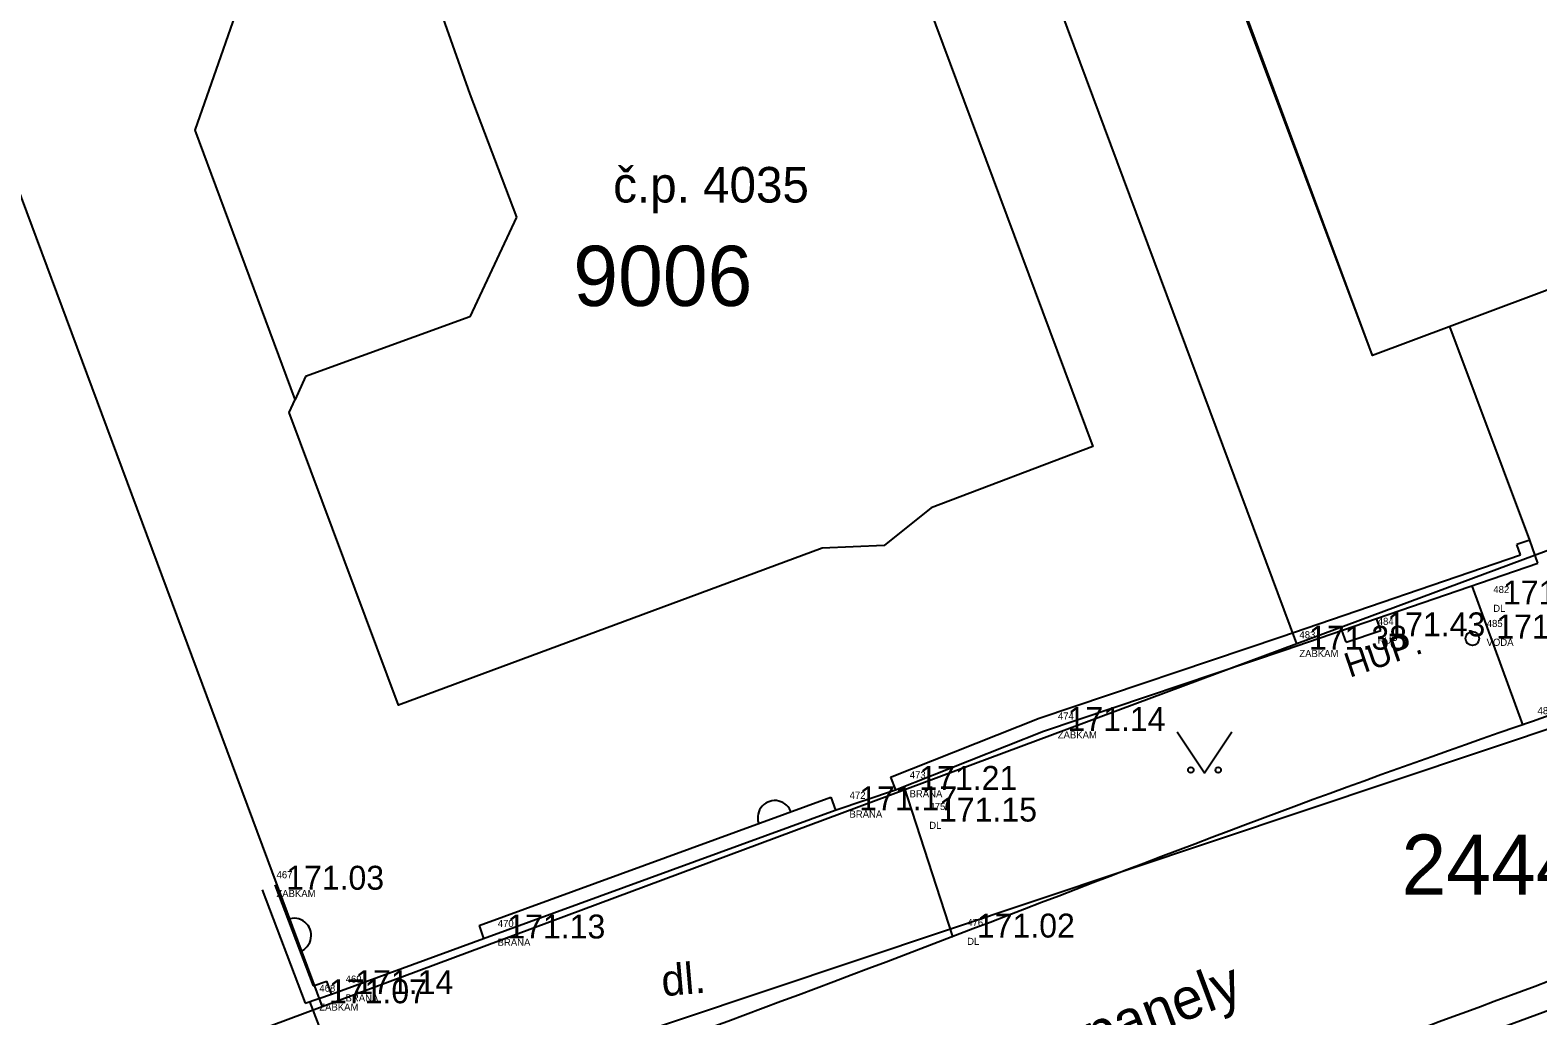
# Model space of a CAD drawing. Extents: x -566117 to -565580, y -1202428 to -1201938.
# Drawn here: x -565883.9 to -565856.36, y -1202030.84 to -1202012.82 of the extents above; entities that cross this region are included whole.
import ezdxf

# ---------------------------------------------------------------- set-up
doc = ezdxf.new("R2010")
doc.units = 0
for name, color, linetype in [('Bod', 7, 'Continuous'), ('BUOVY_NEMĚŘ', 7, 'Continuous'), ('Implicitní', 7, 'Continuous'), ('Katastr', 7, 'Continuous'), ('Kod', 7, 'Continuous'), ('Oplocení', 7, 'Continuous'), ('POMOC_POPIS', 7, 'Continuous'), ('Voda', 7, 'Continuous'), ('Výška', 7, 'Continuous'), ('ZN_KULTUR', 7, 'Continuous'), ('Zpevněné plohy', 7, 'Continuous'), ('Číslo', 7, 'Continuous'), ('Číslo popisné', 7, 'Continuous')]:
    doc.layers.add(name, color=color, linetype=linetype)

# ---------------------------------------------------------------- blocks, each defined once
blk = doc.blocks.new('A$C69D74C1E')
at = {"layer": 'Katastr'}
for p, q in [((205.55, 49.67), (200.77, 62.43)), ((178.35, 59.29), (186.36, 37.77)), ((188.29, 56.62), (189.06, 54.45)), ((175.76, 31.81), (246.67, 55.53)), ((189.06, 54.45), (189.91, 52.2)), ((189.91, 52.2), (189.06, 50.38)), ((211.35, 51.84), (205.55, 49.67)), ((221.98, 51.03), (204.17, 44.4)), ((189.06, 50.38), (186.06, 49.29)), ((186.06, 49.29), (185.87, 48.87)), ((204.17, 44.4), (186.36, 37.77)), ((186.36, 37.77), (175.11, 33.59))]:
    blk.add_line(p, q, dxfattribs=at)
for points in [[(204.17, 44.4), (187.66, 88.74), (186.73, 91.25)], [(197.49, 46.89), (196.63, 46.2), (195.5, 46.15), (187.76, 43.28), (185.76, 48.63), (185.87, 48.87), (184.04, 53.79), (185.12, 56.88), (190.64, 58.91), (191.08, 57.68), (196.13, 59.58), (200.44, 48.01), (197.49, 46.89)]]:
    blk.add_lwpolyline(points, dxfattribs=at)
for s, p in [('9006', (190.95, 50.577)), ('2444/2', (206.08, 39.817))]:
    blk.add_text(s, height=1.1, dxfattribs=at).set_placement(p)
blk = doc.blocks.new('POINT_DISPLAY')
at = {"layer": 'Implicitní'}
blk.add_line((0, 0), (0, 0), dxfattribs=at)
blk = doc.blocks.new('3.140_2')
at = {"layer": 'ZN_KULTUR'}
blk.add_lwpolyline([(-1, 1.5), (0, 0), (1, 1.5)], dxfattribs=at)
for centre in [(-0.5, 0.1), (0.5, 0.1)]:
    blk.add_circle(centre, 0.1, dxfattribs=at)

msp = doc.modelspace()

# ---------------------------------------------------------------- linework, layer by layer
at = {"layer": 'BUOVY_NEMĚŘ'}
msp.add_lwpolyline([(-565853.55, -1201998.93), (-565848.58, -1202012.18), (-565853.93, -1202014.17), (-565853, -1202016.86), (-565853.44, -1202017.03), (-565853.58, -1202016.6), (-565859.38, -1202018.77), (-565865.13, -1202003.26)], close=True, dxfattribs=at)
msp.add_lwpolyline([(-565874.29, -1202009.53), (-565873.85, -1202010.76), (-565868.8, -1202008.86), (-565864.49, -1202020.43), (-565867.44, -1202021.55), (-565868.3, -1202022.24), (-565869.43, -1202022.29), (-565877.17, -1202025.16), (-565879.17, -1202019.81), (-565879.06, -1202019.57), (-565880.89, -1202014.65), (-565879.81, -1202011.56), (-565874.29, -1202009.53)], dxfattribs=at)
at = {"layer": 'Implicitní'}
for p, q in [((-565856.678, -1202022.409), (-565856.743, -1202022.224)), ((-565859.863, -1202024.009), (-565859.228, -1202023.792)), ((-565878.732, -1202030.29), (-565878.481, -1202030.203))]:
    msp.add_line(p, q, dxfattribs=at)
at = {"layer": 'Oplocení'}
for p, q in [((-565856.507, -1202022.141), (-565857.966, -1202018.241)), ((-565856.359, -1202022.563), (-565856.507, -1202022.141)), ((-565861.055, -1202023.908), (-565856.678, -1202022.409)), ((-565860.975, -1202024.145), (-565856.359, -1202022.563)), ((-565865.468, -1202025.394), (-565861.055, -1202023.908)), ((-565865.388, -1202025.631), (-565860.975, -1202024.145)), ((-565868.184, -1202026.474), (-565865.468, -1202025.394)), ((-565868.095, -1202026.707), (-565865.388, -1202025.631)), ((-565868.184, -1202026.474), (-565868.094, -1202026.707)), ((-565869.193, -1202027.079), (-565868.095, -1202026.707)), ((-565875.702, -1202029.185), (-565869.273, -1202026.842)), ((-565875.622, -1202029.422), (-565869.193, -1202027.079)), ((-565869.273, -1202026.842), (-565869.187, -1202027.077)), ((-565879.429, -1202028.443), (-565878.732, -1202030.29)), ((-565879.663, -1202028.531), (-565878.88, -1202030.606)), ((-565875.702, -1202029.185), (-565875.622, -1202029.422)), ((-565878.399, -1202030.439), (-565875.622, -1202029.422)), ((-565878.399, -1202030.439), (-565878.481, -1202030.203)), ((-565878.88, -1202030.606), (-565878.399, -1202030.439))]:
    msp.add_line(p, q, dxfattribs=at)
for centre, start, end in [((-565870.297, -1202027.215), 16.5813, 197.7029), ((-565879.08, -1202029.366), 290.2193, 111.3409)]:
    msp.add_arc(centre, 0.313, start, end, dxfattribs=at)
at = {"layer": 'Voda'}
msp.add_circle((-565857.555, -1202023.94), 0.125, dxfattribs=at)
at = {"layer": 'Zpevněné plohy'}
for p, q in [((-565856.507, -1202022.141), (-565856.743, -1202022.224)), ((-565856.625, -1202025.532), (-565857.559, -1202022.975)), ((-565859.228, -1202023.792), (-565859.303, -1202023.572)), ((-565859.863, -1202024.009), (-565859.938, -1202023.79)), ((-565867.942, -1202026.646), (-565867.05, -1202029.385)), ((-565877.733, -1202033.321), (-565878.79, -1202030.574)), ((-565865.482, -1202034.146), (-565855.383, -1202030.445))]:
    msp.add_line(p, q, dxfattribs=at)
for points in [[(-566046.233, -1202095.491), (-566045.931, -1202095.393), (-566043.978, -1202094.752), (-566040.389, -1202093.195), (-566035.531, -1202091.756), (-566028.975, -1202089.449), (-566022.404, -1202086.74), (-566013.877, -1202083.764), (-566006.988, -1202080.967), (-565999.231, -1202078.336), (-565993.39, -1202076.098), (-565982.391, -1202071.759), (-565967.94, -1202066.641), (-565949.498, -1202059.811), (-565935.388, -1202054.572), (-565926.049, -1202051.077), (-565917.958, -1202048.181), (-565909.827, -1202045.163), (-565898.95, -1202041.321), (-565888.732, -1202037.388), (-565879.759, -1202034.036), (-565869.081, -1202030.224), (-565859.242, -1202026.317), (-565849.297, -1202023.069), (-565843.932, -1202020.848), (-565836.631, -1202018.501), (-565830.04, -1202016.01), (-565822.89, -1202013.251), (-565816.476, -1202011.009), (-565808.989, -1202007.913), (-565802.143, -1202004.887), (-565798.059, -1202002.759), (-565793.947, -1202000.116), (-565789.34, -1201997.072), (-565785.134, -1201994.185), (-565781.539, -1201991.969), (-565778.045, -1201989.73), (-565773.319, -1201986.775), (-565768.281, -1201983.714), (-565761.544, -1201979.725), (-565754.374, -1201977.005), (-565748.201, -1201974.518), (-565743.713, -1201972.786), (-565741.115, -1201971.759), (-565739.444, -1201971.098)], [(-565976.764, -1202074.599), (-565975.068, -1202073.996), (-565970.908, -1202072.515), (-565960.65, -1202068.538), (-565946.466, -1202063.528), (-565932.832, -1202058.326), (-565923.028, -1202054.759), (-565915.71, -1202052.273), (-565903.782, -1202047.572), (-565889.735, -1202042.655), (-565875.782, -1202037.425), (-565865.226, -1202033.562), (-565857.124, -1202030.559), (-565849.222, -1202027.615), (-565843.807, -1202025.74), (-565838.67, -1202023.909), (-565834.175, -1202022.242), (-565830.509, -1202020.913), (-565828.358, -1202020.134)], [(-565860.273, -1202033.863), (-565859.413, -1202033.687), (-565857.722, -1202033.297), (-565854.096, -1202032.103), (-565850.945, -1202030.693), (-565848.598, -1202029.603), (-565848.131, -1202029.386)]]:
    msp.add_open_spline(points, degree=3, dxfattribs=at)

# ---------------------------------------------------------------- block references
at = {"layer": 'Bod'}
for p in [(-565856.507, -1202022.141), (-565856.359, -1202022.563), (-565857.434, -1202023.318), (-565859.546, -1202023.901), (-565857.555, -1202023.94), (-565860.975, -1202024.145), (-565865.388, -1202025.631), (-565856.625, -1202025.532), (-565868.095, -1202026.707), (-565869.193, -1202027.079), (-565867.735, -1202027.285), (-565879.663, -1202028.531), (-565875.622, -1202029.422), (-565867.044, -1202029.405), (-565878.88, -1202030.606), (-565878.399, -1202030.439)]:
    msp.add_blockref('POINT_DISPLAY', p, dxfattribs=at)
at = {"layer": 'Implicitní'}
msp.add_blockref('A$C69D74C1E', (-566064.93, -1202068.44), dxfattribs=at)
at = {"layer": 'ZN_KULTUR', "xscale": 0.5, "yscale": 0.5}
msp.add_blockref('3.140_2', (-565862.448, -1202026.393), dxfattribs=at)

# ---------------------------------------------------------------- texts
at = {"layer": 'Kod'}
for s, p in [('DL', (-565857.174, -1202023.453)), ('HUP', (-565859.286, -1202024.035)), ('VODA', (-565857.295, -1202024.074)), ('ZABKAM', (-565860.716, -1202024.28)), ('ZABKAM', (-565865.129, -1202025.766)), ('BRANA', (-565867.836, -1202026.842)), ('BRANA', (-565868.934, -1202027.213)), ('DL', (-565867.476, -1202027.419)), ('ZABKAM', (-565879.403, -1202028.665)), ('BRANA', (-565875.362, -1202029.556)), ('DL', (-565866.784, -1202029.539)), ('ZABKAM', (-565878.62, -1202030.74)), ('BRANA', (-565878.14, -1202030.573))]:
    msp.add_text(s, height=0.13, dxfattribs=at).set_placement(p)
at = {"layer": 'POMOC_POPIS'}
for s, height, rotation, p in [('HUP.', 0.45, 18.8387, (-565859.796, -1202024.66)), ('dl.', 0.57, 4.9059, (-565872.346, -1202030.479)), ('panely', 0.75, 20.4762, (-565864.477, -1202031.556))]:
    msp.add_text(s, height=height, rotation=rotation, dxfattribs=at).set_placement(p)
at = {"layer": 'Výška'}
for s, p in [('171.54', (-565856.996, -1202023.318)), ('171.43', (-565859.108, -1202023.901)), ('171.38', (-565860.538, -1202024.145)), ('171.47', (-565857.117, -1202023.94)), ('171.14', (-565864.951, -1202025.631)), ('171.21', (-565867.658, -1202026.707)), ('171.17', (-565868.756, -1202027.079)), ('171.15', (-565867.298, -1202027.285)), ('171.03', (-565879.225, -1202028.531)), ('171.13', (-565875.184, -1202029.422)), ('171.02', (-565866.606, -1202029.405)), ('171.14', (-565877.962, -1202030.439)), ('171.07', (-565878.442, -1202030.606))]:
    msp.add_text(s, height=0.4375, dxfattribs=at).set_placement(p)
at = {"layer": 'Číslo'}
for s, p in [('482', (-565857.171, -1202023.109)), ('484', (-565859.283, -1202023.691)), ('485', (-565857.292, -1202023.73)), ('483', (-565860.713, -1202023.936)), ('474', (-565865.126, -1202025.422)), ('481', (-565856.363, -1202025.323)), ('473', (-565867.833, -1202026.498)), ('472', (-565868.931, -1202026.87)), ('475', (-565867.473, -1202027.075)), ('467', (-565879.4, -1202028.321)), ('470', (-565875.359, -1202029.212)), ('476', (-565866.782, -1202029.195)), ('469', (-565878.137, -1202030.229)), ('468', (-565878.618, -1202030.396))]:
    msp.add_text(s, height=0.13, dxfattribs=at).set_placement(p)
at = {"layer": 'Číslo popisné'}
msp.add_text('č.p. 4035', height=0.65, dxfattribs=at).set_placement((-565873.251, -1202015.973))

doc.saveas('drawing.dxf')
